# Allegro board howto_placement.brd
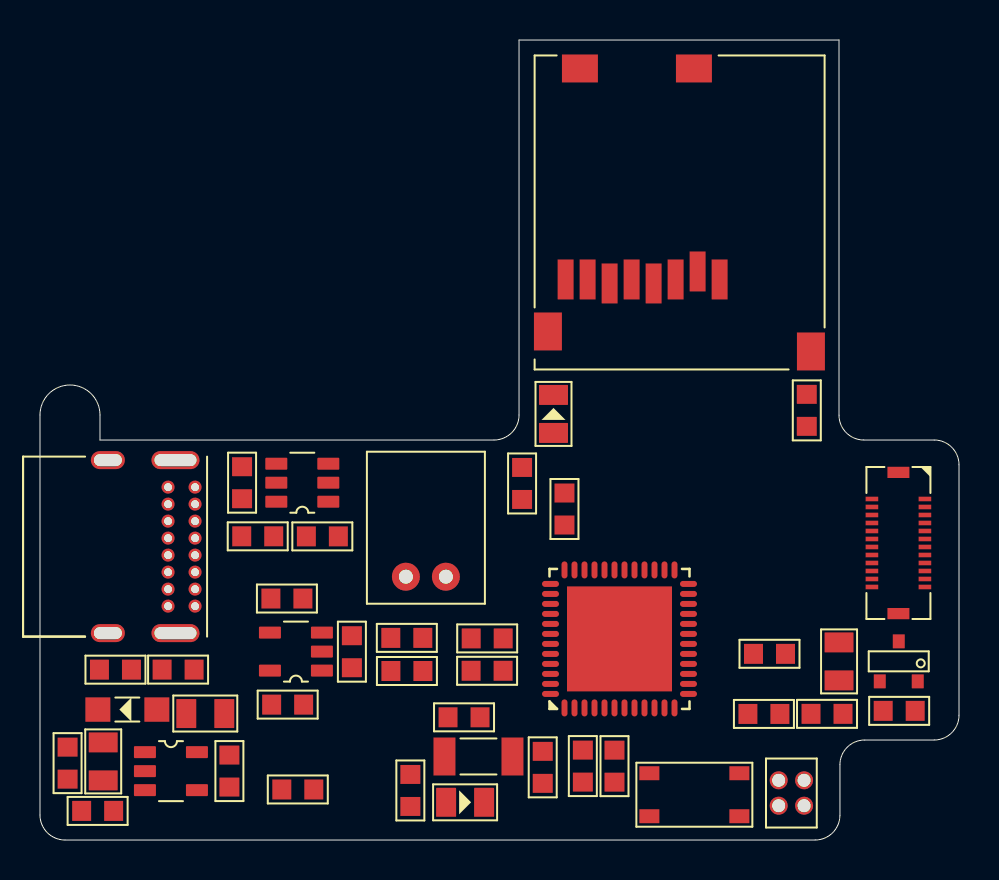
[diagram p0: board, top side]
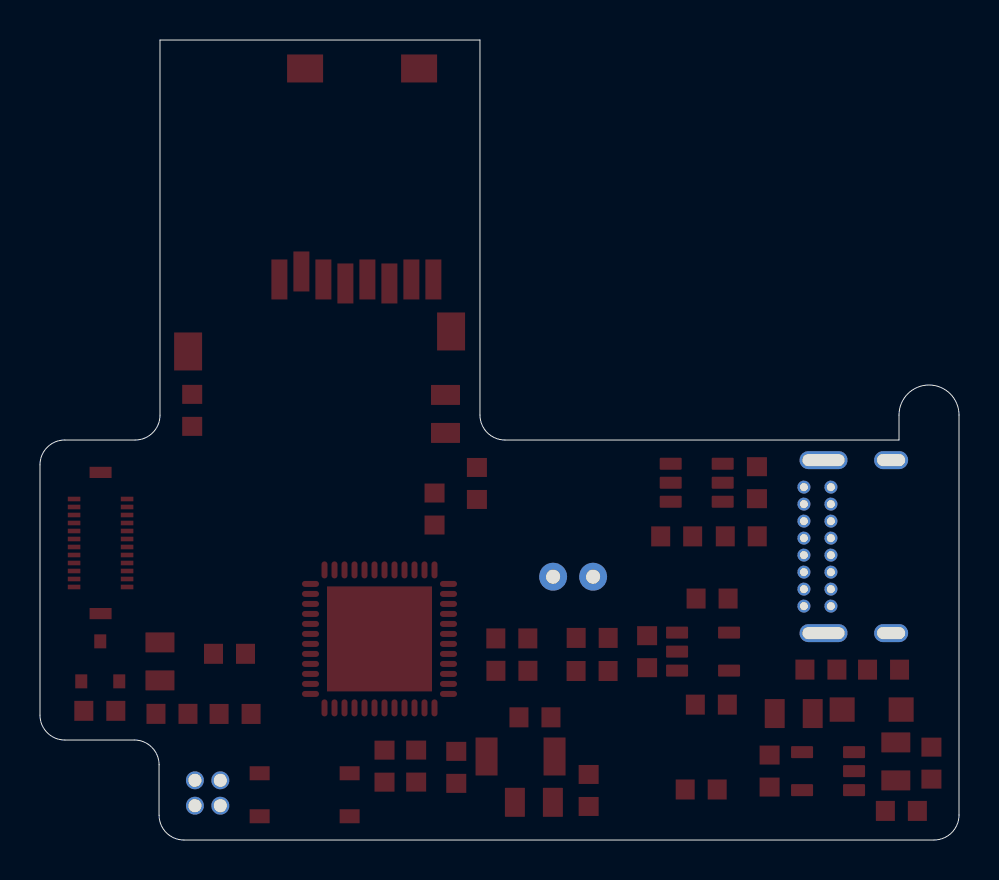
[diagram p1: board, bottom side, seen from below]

Outline 45.95 x 40 mm; copper layers: TOP, L2, L3, BOTTOM. Coordinates in mm from the lower left corner of the outline.
Outline path: 0,21.25 0,1.25 arc(0.37,0.37) 1.25,0 38.76,0 arc(39.64,0.36) 40,1.24 40,3.76 arc(40.36,4.64) 41.24,5 44.71,5 arc(45.59,5.36) 45.95,6.24 45.95,18.76 arc(45.59,19.64) 44.71,20 41.19,20 arc(40.32,20.36) 39.95,21.24 39.95,40 23.95,40 23.95,21.25 arc(23.59,20.37) 22.7,20 3,20 3,21.25 arc(1.5,22.75) 0,21.25

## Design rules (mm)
constraint set DEFAULT: min track width 0.127

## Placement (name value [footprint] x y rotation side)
C15  1uF  [CAP0603]  10.1 17.86 270 top
C16  1uF  [CAP0603]  15.6 9.42 270 top
C19  10uF  [CAP0805]  3.16 3.93 270 top
C20  2.2uF  [CAP0603]  12.38 6.77 0 top
C21  470pF  [CAP0603]  12.35 12.07 0 top
C23  100nF  [CAP0603]  28.73 3.69 270 top
C24  100nF  [CAP0603]  26.23 16.55 90 top
C25  100nF  [CAP0603]  36.48 9.31 0 top
C26  100nF  [CAP0603]  22.36 8.46 180 top
C27  1uF  [CAP0603]  22.36 10.08 180 top
C28  1uF  [CAP0603]  27.14 3.7 270 top
C29  100nF  [CAP0603]  39.35 6.31 0 top
C32  1uF  [CAP0603]  9.47 3.45 270 top
C33  9pF  [CAP0603]  21.2 6.13 180 top
C34  9pF  [CAP0603]  25.14 3.63 270 top
D1  GREEN  [DIO0805]  21.26 1.88 0 top
D2  GREEN  [DIO0805]  25.68 21.3 90 top
D3  SCHOTTKY_DIODE  [SOD-123FL]  4.37 6.52 180 top
J1  -  [USB4085-GF-A]  1.65 14.67 270 top
J2  HEADER VERT 2X2  [2X2-HEADER-50MIL-VERT]  37.57 2.35 270 top
J3  DF37NB-24DS-0.4V  [DF37NB-24DS-0]  42.92 14.85 270 top
J4  2-PIN-CON  [S2B-PH-K]  18.3 13.16 0 top
L1  10uH  [IND0805]  8.26 6.32 180 top
M2  NMOS  [SOT-23-3]  42.94 8.93 0 top
R7  86.6k  [RES0603]  1.38 3.84 270 top
R8  10k  [RES0603]  2.88 1.45 0 top
R9  5.1k  [RES0603]  3.77 8.52 0 top
R10  5.1k  [RES0603]  6.9 8.52 0 top
R11  5.1k  [RES0603]  10.89 15.18 0 top
R12  10k  [RES0603]  36.2 6.3 0 top
R13  10k  [RES0603]  12.89 2.53 0 top
R14  10k  [RES0603]  18.52 2.48 270 top
R15  1.5k  [RES0603]  24.11 17.83 90 top
R16  100k  [RES0603]  18.34 10.11 0 top
R17  100k  [RES0603]  18.35 8.45 180 top
R18  10k  [RES0603]  38.34 21.48 270 top
R19  150R  [RES0805]  39.96 8.93 90 top
R20  10k  [RES0603]  42.96 6.46 0 top
R21  10k  [RES0603]  14.12 15.18 180 top
S1  SPST-NO  [PTS815-SJM-250-SMTR-LFS]  32.72 2.26 0 top
SD2  -  [MEM2061]  30.13 28.03 0 top
U2  BQ21040  [SOT-23-6]  13.12 17.86 180 top
U4  MIC5205-3.3YM5-TR  [SOT-23-5]  12.8 9.42 180 top
U5  AP3012_IC  [SOT-23-5]  6.55 3.44 0 top
U7  ATSAMD21G18A-MF  [48QFN_7X7]  28.98 10.05 90 top
Y2  32.768 kHz  [2-SMD]  21.93 4.18 0 top

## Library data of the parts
C15 C16 C19-C21 C23-C29 C32-C34 = CAP1: tolerance: 10%
D1 D2 = SML-210MTT86
D3 = SCHOTTKY_DIODE
J1 = USB4085-GF-A
J2 = HEADER VERT 2X2
J3 = DF37NB-24DS-0.4V
J4 = 2-PIN-CON
L1 = IND: tolerance: 20%
M2 = NMOS
R7-R21 = RES1: tolerance: 1%
S1 = PTS815 SJM 250 SMTR LFS
SD2 = MEM2061
U2 = BQ21040
U4 = MIC5205-3.3YM5-TR
U5 = AP3012_IC
U7 = ATSAMD21G18A-MF
Y2 = CC5V-T1A-32.768KHZ-9PF: tolerance: 20%

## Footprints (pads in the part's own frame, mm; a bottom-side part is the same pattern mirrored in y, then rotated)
2-SMD
  rect 1.1x1.9 smd: 1(-1.7,0) 2(1.7,0)
2X2-HEADER-50MIL-VERT
  round 0.9 hole 0.65: 1(-0.635,0.635) 2(-0.635,-0.635) 3(0.635,0.635) 4(0.635,-0.635)
48QFN_7X7
  oval 0.851x0.3 smd: 1(-3.45,2.75) 2(-3.45,2.25) 3(-3.45,1.75) 4(-3.45,1.25) 5(-3.45,0.75) 6(-3.45,0.25) 7(-3.45,-0.25) 8(-3.45,-0.75) 9(-3.45,-1.25) 10(-3.45,-1.75) 11(-3.45,-2.25) 12(-3.45,-2.75) 25(3.45,-2.75) 26(3.45,-2.25) 27(3.45,-1.75) 28(3.45,-1.25) 29(3.45,-0.75) 30(3.45,-0.25) 31(3.45,0.25) 32(3.45,0.75) 33(3.45,1.25) 34(3.45,1.75) 35(3.45,2.25) 36(3.45,2.75)
  oval 0.3x0.851 smd: 13(-2.75,-3.45) 14(-2.25,-3.45) 15(-1.75,-3.45) 16(-1.25,-3.45) 17(-0.75,-3.45) 18(-0.25,-3.45) 19(0.25,-3.45) 20(0.75,-3.45) 21(1.25,-3.45) 22(1.75,-3.45) 23(2.25,-3.45) 24(2.75,-3.45) 37(2.75,3.45) 38(2.25,3.45) 39(1.75,3.45) 40(1.25,3.45) 41(0.75,3.45) 42(0.25,3.45) 43(-0.25,3.45) 44(-0.75,3.45) 45(-1.25,3.45) 46(-1.75,3.45) 47(-2.25,3.45) 48(-2.75,3.45)
  rect 5.25x5.25 smd: 49(0,0)
CAP0603
  rect 0.95x1.001 smd: 1(-0.8,0) 2(0.8,0)
CAP0805
  rrect 1x1.45 smd: 1(-0.95,0) 2(0.95,0)
DF37NB-24DS-0
  rect 0.23x0.63 smd: 1(-2.2,1.325) 2(-2.2,-1.325) 3(-1.8,1.325) 4(-1.8,-1.325) 5(-1.4,1.325) 6(-1.4,-1.325) 7(-1,1.325) 8(-1,-1.325) 9(-0.6,1.325) 10(-0.6,-1.325) 11(-0.2,1.325) 12(-0.2,-1.325) 13(0.2,1.325) 14(0.2,-1.325) 15(0.6,1.325) 16(0.6,-1.325) 17(1,1.325) 18(1,-1.325) 19(1.4,1.325) 20(1.4,-1.325) 21(1.8,1.325) 22(1.8,-1.325) 23(2.2,1.325) 24(2.2,-1.325)
  rect 0.56x1.1 smd: 25(-3.53,0) 26(3.53,0)
DIO0805
  rrect 1x1.45 smd: 1(-0.95,0) 2(0.95,0)
IND0805
  rrect 1x1.45 smd: 1(-0.95,0) 2(0.95,0)
MEM2061
  rect 0.8x2 smd: 1(3.85,0) 2(2.75,0.4) 3(1.65,0) 4(0.55,-0.2) 5(-0.55,0) 6(-1.65,-0.2) 7(-2.75,0) 8(-3.85,0)
  rect 1.4x1.9 smd: P1(-4.735,-2.6) P2(8.415,-3.6)
  rect 1.8x1.4 smd: SW1(-3.135,10.55) SW2(2.565,10.55)
PTS815-SJM-250-SMTR-LFS
  rect 1x0.7 smd: 1(-2.25,1.075) 2(2.25,1.075) 3(-2.25,-1.075) 4(2.25,-1.075)
RES0603
  rect 0.95x1.001 smd: 1(-0.8,0) 2(0.8,0)
RES0805
  rrect 1x1.45 smd: 1(-0.95,0) 2(0.95,0)
S2B-PH-K
  round 1.4 hole 0.7: 1(2,0) 2(0,0)
SOD-123FL
  rect 1.25x1.22 smd: 1(-1.475,0) 2(1.475,0)
SOT-23-3
  rect 0.6x0.7 smd: 1(0.95,-1) 2(0,1) 3(-0.95,-1)
SOT-23-5
  rrect 1.1x0.6 smd: 1(-1.3,0.95) 2(-1.3,0) 3(-1.3,-0.95) 4(1.3,-0.95) 5(1.3,0.95)
SOT-23-6
  rrect 1.1x0.6 smd: 1(-1.3,0.95) 2(-1.3,0) 3(-1.3,-0.95) 4(1.3,-0.95) 5(1.3,0) 6(1.3,0.95)
USB4085-GF-A
  oval 0.9x1.7 hole 0.6x1.4 unplated: (-4.325,1.74) (4.325,1.74)
  round 0.65 hole 0.4: A1(-2.975,6.1) A4(-2.125,6.1) A5(-1.275,6.1) A6(-0.425,6.1) A7(0.425,6.1) A8(1.275,6.1) A9(2.125,6.1) A12(2.975,6.1) B1(2.975,4.75) B4(2.125,4.75) B5(1.275,4.75) B6(0.425,4.75) B7(-0.425,4.75) B8(-1.275,4.75) B9(-2.125,4.75) B12(-2.975,4.75)
  oval 0.9x2.4 hole 0.6x2.1: MNT1(-4.325,5.12) MNT2(4.325,5.12)

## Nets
+3V3: C20.1 C23.1 C24.1 C25.1 C26.1 J2.3 J3.18 J3.20 R12.1 R18.1 SD2.4 U4.5(OUT) U7.6 U7.17 U7.36(VDDIO#36) U7.44
+12V0: C19.1 D3.2 R7.1 R19.1
+VBATT: C16.1 C32.1 J4.1 L1.1 R15.1 R16.1 U2.2 U4.1 U4.3 U5.5(VIN)
+VDDCORE: C27.1 U7.43
GND: C15.2 C16.2 C19.2 C20.2 C21.2 C23.2 C24.2 C25.2 C26.2 C27.2 C28.2 C29.2 C32.2 C33.2 C34.2 D1.2(K) J1.A1 J1.A12 J1.B1 J1.B12 J1.MNT1 J1.MNT2 J2.4 J3.1 J3.3 J3.13 J3.21 J3.24 J3.25 J3.26 J4.2 M2.1(S) R8.2 R9.2 R10.2 R11.2 R13.2 R17.2 R20.2 R21.2 S1.1 S1.3 SD2.6(VSS) SD2.P1 SD2.P2 SD2.SW2 U2.5 U4.2 U5.2 U7.5 U7.18 U7.35 U7.42 U7.49
+V_USB: C15.1 J1.A4 J1.A9 J1.B4 J1.B9(VBUS4) U2.6(VIN)
ADC_VBATT: R16.2 R17.1 U7.48
AREF: C28.1 U7.4
CS*: J3.17 U7.14
D_N: J1.A7 J1.B7 U7.33
D_P: J1.A6 J1.B6 U7.34
DB0: J3.12 U7.26
DB1: J3.11 U7.16
DB2: J3.10 U7.27
DB3: J3.9 U7.19
DB4: J3.8 U7.28
DB5: J3.7 U7.21
DB6: J3.6 U7.29
DB7: J3.5 U7.22
LCD_POWER_EN: R13.1 U5.4 U7.39
LCD_PWM: M2.3 R20.1 U7.20
LCD_RST: J3.2 U7.30
RD*: J3.14 U7.24
RS: J3.16 U7.23
SD_CARD_DETECT: R18.2 SD2.SW1 U7.13
SD_CS: SD2.2 U7.32
SD_MISO: SD2.7 U7.38
SD_MOSI: SD2.3 U7.31
SD_SCK: SD2.5 U7.37
SWCLK: J2.1 U7.45
SWDIO: J2.2 U7.46
WR*: J3.15 U7.15
N42146: J1.A5 R9.1
N42214: R11.1 U2.4
N42218: R21.1 U2.1
N42238: C21.1 U4.4
N42330: J1.B5 R10.1
N42350: D2.1 R15.2
N42414: D2.2(K) U2.3
N42648: D3.1 L1.2 U5.1
N42818: R7.2 R8.1 U5.3
N43960: C33.1 U7.1 Y2.1
N43976: C34.1 U7.2 Y2.2
N44106: C29.1 R12.2 S1.2 S1.4 U7.40
N44702: R14.1 U7.25
N44714: D1.1 R14.2
N46598: J3.22 R19.2
N46734: J3.23 M2.2

Pads without a net: J1 A8 B8; J3 4 19; SD2 1 8; U7 3 7 8 9 10 11 12 41 47
